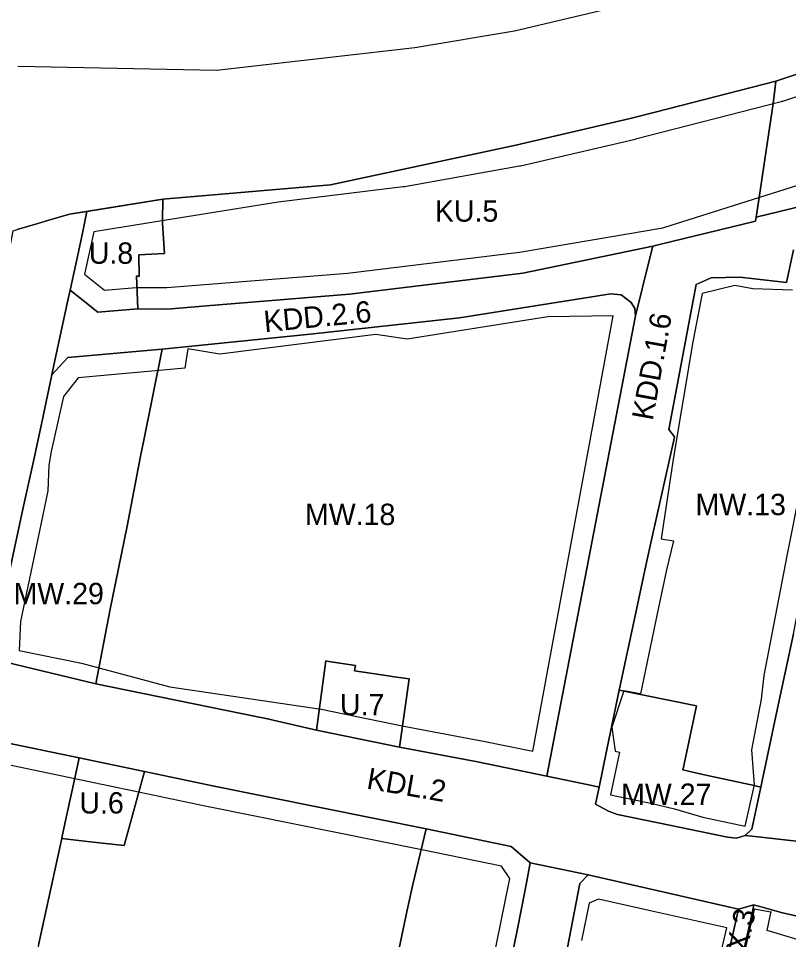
# Model space of a CAD drawing. Extents: x 7421913 to 7423341, y 5550123 to 5551175.
# Drawn here: x 7422221.1 to 7422401.5, y 5550727.7 to 5550943.3 of the extents above; entities that cross this region are included whole.
import ezdxf

# ---------------------------------------------------------------- set-up
doc = ezdxf.new("R2010")
doc.units = 0
for name, color, linetype in [('linie_rozgraniczajace', 7, 'Continuous'), ('linie_zabudowy_nieprzekraczalne', 7, 'Continuous'), ('oznaczenia_przeznaczen', 7, 'Continuous')]:
    doc.layers.add(name, color=color, linetype=linetype)

msp = doc.modelspace()

# ---------------------------------------------------------------- linework, layer by layer
at = {"layer": 'linie_rozgraniczajace'}
for points in [[(7422220.98, 5550932.17), (7422267.53, 5550931.27), (7422313.91, 5550936.52), (7422337.26, 5550940.47), (7422374.26, 5550949.25), (7422409.76, 5550960.93), (7422437.33, 5550971.35), (7422441.45, 5550972.91), (7422471.77, 5550984.38), (7422488.78, 5550990.81), (7422507.92, 5550998.54), (7422528.96, 5551007.2), (7422549.46, 5551014.98), (7422566.39, 5551020.72), (7422600.97, 5551030.45), (7422637.74, 5551037.63), (7422706.25, 5551050.46), (7422774.99, 5551065.83), (7422840.21, 5551081.98)], [(7422487.44, 5550952.92), (7422458.59, 5550942.31), (7422440.1, 5550939.32), (7422431.14, 5550942.19), (7422416.39, 5550936.46), (7422412.46, 5550934.94), (7422412.25, 5550934.1), (7422412.12, 5550933.61), (7422403.43, 5550930.26), (7422398.51, 5550928.69), (7422370.22, 5550921.41), (7422364.38, 5550919.91), (7422337.59, 5550913.65), (7422294.17, 5550904.39), (7422254.92, 5550901.03), (7422233.03, 5550897.49), (7422228.24, 5550896.09), (7422225.63, 5550895.33), (7422220.81, 5550893.92)], [(7422402.63, 5550889.21), (7422401, 5550881.52), (7422390.04, 5550882.81), (7422383.35, 5550882.62), (7422379.85, 5550881.03), (7422373.43, 5550847.12), (7422374.78, 5550845.38), (7422374.61, 5550844.64), (7422369.53, 5550821.98), (7422368.03, 5550815.31), (7422365.83, 5550804.99), (7422361.79, 5550786.12), (7422358.91, 5550772.22), (7422357.09, 5550763.43), (7422355.4, 5550763.78), (7422344.84, 5550765.96), (7422365.63, 5550873.73), (7422367.2, 5550880.07), (7422369.15, 5550887.93), (7422369.68, 5550890.05), (7422371.88, 5550890.58), (7422376.72, 5550891.74), (7422393.4, 5550895.8), (7422393.74, 5550895.88), (7422393.88, 5550896.84), (7422404.82, 5550899.45)], [(7422402.67, 5550799.3), (7422398.8, 5550781.52), (7422394.98, 5550763.42), (7422393.44, 5550763.78), (7422383.62, 5550765.92), (7422380.72, 5550766.55), (7422376.71, 5550767.42), (7422376.76, 5550767.69), (7422376.92, 5550768.48), (7422377.62, 5550771.73), (7422379.89, 5550782.4), (7422361.79, 5550786.12), (7422365.83, 5550804.99), (7422368.03, 5550815.31), (7422369.53, 5550821.98), (7422374.61, 5550844.64), (7422374.78, 5550845.38), (7422373.43, 5550847.12), (7422379.85, 5550881.03), (7422383.35, 5550882.62), (7422390.04, 5550882.81), (7422401, 5550881.52), (7422402.63, 5550889.21)], [(7422218.17, 5550792.64), (7422239.26, 5550787.57), (7422277.08, 5550779.86), (7422278.76, 5550779.52), (7422290.94, 5550776.76), (7422310.39, 5550772.77), (7422328.26, 5550769.39), (7422344.84, 5550765.96), (7422355.4, 5550763.78), (7422357.09, 5550763.43), (7422356.25, 5550759.4), (7422359.3, 5550757.74), (7422361.38, 5550757), (7422373.96, 5550754.42), (7422387.19, 5550751.67), (7422389.29, 5550751.47), (7422391.33, 5550752.11), (7422393.67, 5550751.85), (7422404, 5550750.7)], [(7422436.89, 5550725.5), (7422425.59, 5550727.79), (7422410.79, 5550730.73), (7422411.25, 5550731.36), (7422403.89, 5550733.09), (7422400.05, 5550733.99), (7422393.38, 5550735.82), (7422389.77, 5550734.83), (7422370.59, 5550739.24), (7422354.55, 5550742.84), (7422340.93, 5550745.68), (7422336.5, 5550749.5), (7422316.61, 5550753.63), (7422266.97, 5550763.62), (7422250.63, 5550767.05), (7422241.68, 5550768.92), (7422235.34, 5550770.25), (7422213.4, 5550774.82)], [(7422213.4, 5550774.82), (7422235.34, 5550770.25), (7422234.28, 5550765.52), (7422232.46, 5550757.03), (7422231.35, 5550751.91), (7422231.24, 5550751.35), (7422230.09, 5550746.05), (7422225.78, 5550726.41), (7422221.66, 5550706.89), (7422221.26, 5550704.88), (7422221.11, 5550704.1), (7422217.38, 5550687.41)], [(7422225.78, 5550726.41), (7422230.09, 5550746.05), (7422231.24, 5550751.35), (7422237.9, 5550750.63), (7422245.87, 5550749.77), (7422250.63, 5550767.05), (7422266.97, 5550763.62), (7422316.61, 5550753.63), (7422313.46, 5550740.58), (7422312.18, 5550734.61), (7422310.91, 5550728.65), (7422309.63, 5550722.69)], [(7422309.63, 5550722.69), (7422310.91, 5550728.65), (7422312.18, 5550734.61), (7422313.46, 5550740.58), (7422316.61, 5550753.63), (7422336.5, 5550749.5), (7422340.93, 5550745.68), (7422340.21, 5550741.37), (7422339.01, 5550735.36), (7422337.8, 5550729.42), (7422336.62, 5550723.39)], [(7422336.62, 5550723.39), (7422337.8, 5550729.42), (7422339.01, 5550735.36), (7422340.21, 5550741.37), (7422340.93, 5550745.68), (7422354.55, 5550742.84), (7422352.62, 5550740.82), (7422350.11, 5550727.89), (7422347.79, 5550715.72)], [(7422347.79, 5550715.72), (7422350.11, 5550727.89), (7422352.62, 5550740.82), (7422354.55, 5550742.84), (7422370.59, 5550739.24), (7422389.77, 5550734.83), (7422386.06, 5550718.57)]]:
    msp.add_lwpolyline(points, dxfattribs=at)
for points in [[(7422404.82, 5550899.45), (7422393.88, 5550896.84), (7422394.59, 5550901.4), (7422397.89, 5550923.41), (7422398.27, 5550926.65), (7422398.51, 5550928.69), (7422403.43, 5550930.26), (7422412.12, 5550933.61), (7422412.25, 5550934.1), (7422412.46, 5550934.94), (7422416.39, 5550936.46), (7422431.14, 5550942.19), (7422429, 5550931.44), (7422425.22, 5550912.43), (7422423.53, 5550903.95)], [(7422254.92, 5550901.03), (7422294.17, 5550904.39), (7422337.59, 5550913.65), (7422364.38, 5550919.91), (7422370.22, 5550921.41), (7422398.51, 5550928.69), (7422398.27, 5550926.65), (7422397.89, 5550923.41), (7422394.59, 5550901.4), (7422393.88, 5550896.84), (7422393.74, 5550895.88), (7422393.4, 5550895.8), (7422376.72, 5550891.74), (7422371.88, 5550890.58), (7422369.68, 5550890.05), (7422339.28, 5550883.68), (7422298.68, 5550878.76), (7422265.17, 5550876.07), (7422256.05, 5550875.32), (7422249.09, 5550875.36), (7422248.73, 5550883.07), (7422249.37, 5550882.92), (7422249.29, 5550888.04), (7422252.28, 5550888.19), (7422255.28, 5550888.34), (7422254.87, 5550895.34), (7422254.83, 5550895.99), (7422254.88, 5550895.99)], [(7422233.22, 5550879.76), (7422234.52, 5550885.8), (7422236.08, 5550893.09), (7422237.14, 5550898.15), (7422254.92, 5550901.03), (7422254.88, 5550895.99), (7422254.83, 5550895.99), (7422254.87, 5550895.34), (7422255.28, 5550888.34), (7422252.28, 5550888.19), (7422249.29, 5550888.04), (7422249.37, 5550882.92), (7422248.73, 5550883.07), (7422249.09, 5550875.36), (7422239.72, 5550874.56)], [(7422218.13, 5550809.87), (7422216.61, 5550802.89), (7422215.46, 5550803.43), (7422210.18, 5550805.96), (7422209.07, 5550806.49), (7422206.35, 5550807.8), (7422203.81, 5550809.68), (7422219.88, 5550893.65), (7422220.81, 5550893.92), (7422225.63, 5550895.33), (7422228.24, 5550896.09), (7422233.03, 5550897.49), (7422237.14, 5550898.15), (7422236.08, 5550893.09), (7422234.52, 5550885.8), (7422233.22, 5550879.76), (7422232.78, 5550877.73), (7422229.43, 5550862.16), (7422228.94, 5550859.89), (7422226.56, 5550848.79), (7422225.93, 5550845.85), (7422224.91, 5550841.13), (7422222.32, 5550829.17)], [(7422367.2, 5550880.07), (7422365.63, 5550873.73), (7422365.45, 5550875.47), (7422364.61, 5550876.81), (7422362.31, 5550878.65), (7422359.85, 5550878.91), (7422324.42, 5550873.29), (7422289.47, 5550869.45), (7422254.74, 5550865.96), (7422232.68, 5550864), (7422228.94, 5550859.89), (7422229.43, 5550862.16), (7422232.78, 5550877.73), (7422233.22, 5550879.76), (7422239.72, 5550874.56), (7422249.09, 5550875.36), (7422256.05, 5550875.32), (7422265.17, 5550876.07), (7422298.68, 5550878.76), (7422339.28, 5550883.68), (7422369.68, 5550890.05), (7422369.15, 5550887.93)], [(7422429.98, 5550882.78), (7422423.8, 5550851.32), (7422423.18, 5550848.17), (7422422.74, 5550845.9), (7422421.6, 5550840.11), (7422420.88, 5550836.46), (7422412.36, 5550793.58), (7422404.93, 5550755.58), (7422404, 5550750.7), (7422393.67, 5550751.85), (7422391.33, 5550752.11), (7422392.9, 5550753.58), (7422394.98, 5550763.42), (7422398.8, 5550781.52), (7422402.67, 5550799.3), (7422406.26, 5550817.72), (7422411.97, 5550845.88), (7422415.62, 5550865.28), (7422419.77, 5550885.08), (7422429.13, 5550882.96)], [(7422246.55, 5550824.45), (7422249.81, 5550841.29), (7422250.39, 5550844.23), (7422254.74, 5550865.96), (7422289.47, 5550869.45), (7422324.42, 5550873.29), (7422359.85, 5550878.91), (7422362.31, 5550878.65), (7422364.61, 5550876.81), (7422365.45, 5550875.47), (7422365.63, 5550873.73), (7422344.84, 5550765.96), (7422328.26, 5550769.39), (7422310.39, 5550772.77), (7422312.63, 5550788.72), (7422309.12, 5550789.25), (7422307.68, 5550789.46), (7422299.84, 5550790.63), (7422300.05, 5550791.88), (7422293.8, 5550792.83), (7422293.13, 5550792.93), (7422290.94, 5550776.76), (7422278.76, 5550779.52), (7422277.08, 5550779.86), (7422239.26, 5550787.57), (7422242.62, 5550805.06)], [(7422242.62, 5550805.06), (7422239.26, 5550787.57), (7422218.17, 5550792.64), (7422216.18, 5550795.44), (7422216.61, 5550802.89), (7422218.13, 5550809.87), (7422222.32, 5550829.17), (7422224.91, 5550841.13), (7422225.93, 5550845.85), (7422226.56, 5550848.79), (7422228.94, 5550859.89), (7422232.68, 5550864), (7422254.74, 5550865.96), (7422250.39, 5550844.23), (7422249.81, 5550841.29), (7422246.55, 5550824.45)], [(7422310.39, 5550772.77), (7422290.94, 5550776.76), (7422293.13, 5550792.93), (7422293.8, 5550792.83), (7422300.05, 5550791.88), (7422299.84, 5550790.63), (7422307.68, 5550789.46), (7422309.12, 5550789.25), (7422312.63, 5550788.72)], [(7422394.98, 5550763.42), (7422392.9, 5550753.58), (7422391.33, 5550752.11), (7422389.29, 5550751.47), (7422387.19, 5550751.67), (7422373.96, 5550754.42), (7422361.38, 5550757), (7422359.3, 5550757.74), (7422356.25, 5550759.4), (7422357.09, 5550763.43), (7422358.91, 5550772.22), (7422361.79, 5550786.12), (7422379.89, 5550782.4), (7422377.62, 5550771.73), (7422376.92, 5550768.48), (7422376.76, 5550767.69), (7422376.71, 5550767.42), (7422380.72, 5550766.55), (7422383.62, 5550765.92), (7422393.44, 5550763.78)], [(7422250.63, 5550767.05), (7422245.87, 5550749.77), (7422237.9, 5550750.63), (7422231.24, 5550751.35), (7422231.35, 5550751.91), (7422232.46, 5550757.03), (7422234.28, 5550765.52), (7422235.34, 5550770.25), (7422241.68, 5550768.92)], [(7422388.85, 5550715.6), (7422386.06, 5550718.57), (7422389.77, 5550734.83), (7422393.38, 5550735.82), (7422392.79, 5550733.16), (7422391.17, 5550725.97)], [(7422454.96, 5550722.08), (7422451.28, 5550712.14), (7422483.54, 5550700.93), (7422481.91, 5550688.66), (7422474.43, 5550684.56), (7422444.95, 5550694.93), (7422433.33, 5550699.08), (7422427.58, 5550701.09), (7422417.05, 5550704.79), (7422403.17, 5550709.84), (7422389.47, 5550714.93), (7422388.85, 5550715.6), (7422391.17, 5550725.97), (7422392.79, 5550733.16), (7422393.38, 5550735.82), (7422400.05, 5550733.99), (7422403.89, 5550733.09), (7422411.25, 5550731.36), (7422410.79, 5550730.73), (7422425.59, 5550727.79), (7422436.89, 5550725.5), (7422442.35, 5550724.39)]]:
    msp.add_lwpolyline(points, close=True, dxfattribs=at)
at = {"layer": 'linie_zabudowy_nieprzekraczalne'}
for points in [[(7422404.95, 5550925.5), (7422400.03, 5550923.93), (7422399.8, 5550923.86), (7422399.76, 5550923.85), (7422365.63, 5550915.07), (7422365.52, 5550915.04), (7422338.73, 5550908.78), (7422338.57, 5550908.75), (7422338.47, 5550908.73), (7422311.51, 5550903.93), (7422311.28, 5550903.89), (7422311.23, 5550903.89), (7422281.93, 5550900.33), (7422255.72, 5550896.09), (7422238.79, 5550893.37), (7422236.6, 5550883.46), (7422241.28, 5550879.71), (7422248.66, 5550880.34), (7422248.76, 5550880.35), (7422249.09, 5550880.36), (7422249.12, 5550880.36), (7422255.86, 5550880.32), (7422264.76, 5550881.05), (7422264.77, 5550881.05), (7422298.17, 5550883.74), (7422338.47, 5550888.62), (7422372.01, 5550894.36), (7422403.66, 5550904.31)], [(7422402.4, 5550879.72), (7422393.12, 5550880.04), (7422388.92, 5550880.82), (7422381.22, 5550878.99), (7422379.06, 5550867.66), (7422374.5, 5550840.65), (7422371.62, 5550821.56), (7422374.5, 5550821.04), (7422372.91, 5550814.24), (7422370.72, 5550803.95), (7422370.72, 5550803.94), (7422366.79, 5550785.22), (7422362.91, 5550785.96), (7422360.08, 5550777.41), (7422360.87, 5550771.85), (7422361.92, 5550771.59), (7422359.77, 5550761.62), (7422369.52, 5550759.53), (7422374.76, 5550758.32), (7422381.42, 5550756.33), (7422391.32, 5550754.25), (7422393.49, 5550763.93), (7422392.91, 5550772.11), (7422395.16, 5550784.02), (7422395.79, 5550789.57), (7422401.14, 5550817.58), (7422404.34, 5550833.63)], [(7422345.09, 5550873.47), (7422312.15, 5550868.25), (7422304.81, 5550869.37), (7422268.28, 5550864.75), (7422260.81, 5550866.01), (7422260.08, 5550861.49), (7422235.07, 5550859.19), (7422231.64, 5550854.87), (7422230.34, 5550848.9), (7422228.75, 5550842), (7422228.19, 5550838.74), (7422228.01, 5550832.77), (7422226.05, 5550823.36), (7422221.58, 5550802.21), (7422221.3, 5550795.39), (7422235.84, 5550792.41), (7422256.54, 5550786.91), (7422291.99, 5550781.65), (7422311.36, 5550777.68), (7422329.19, 5550774.3), (7422329.24, 5550774.29), (7422329.27, 5550774.29), (7422341.61, 5550771.79), (7422360.38, 5550873.72), (7422345.09, 5550873.47)], [(7422324.7, 5550685.55), (7422336.17, 5550742.05), (7422334.22, 5550744.87), (7422315.61, 5550748.73), (7422265.98, 5550758.72), (7422265.94, 5550758.73), (7422249.61, 5550762.16), (7422240.66, 5550764.03), (7422240.65, 5550764.03), (7422234.32, 5550765.36), (7422214.9, 5550769.4)], [(7422357, 5550737.16), (7422354.76, 5550736.26), (7422352.98, 5550727.49)], [(7422382.17, 5550709.87), (7422387.01, 5550730.48), (7422369.48, 5550734.36), (7422357, 5550737.16)], [(7422397.31, 5550734.1), (7422393.4, 5550734.85), (7422389.39, 5550716.95), (7422402.44, 5550712.28), (7422408.31, 5550709.95), (7422417.64, 5550706.69), (7422427.89, 5550702.59), (7422456.51, 5550692.24), (7422459.96, 5550690), (7422467.33, 5550687.39), (7422480.75, 5550693.45), (7422482.8, 5550707.62), (7422483.27, 5550712.28), (7422460.61, 5550720.12), (7422459.4, 5550716.2), (7422441.37, 5550719.49), (7422441.35, 5550719.49), (7422435.9, 5550720.6), (7422424.61, 5550722.89), (7422409.18, 5550726), (7422396.47, 5550729.81), (7422397.4, 5550734.29)]]:
    msp.add_lwpolyline(points, dxfattribs=at)

# ---------------------------------------------------------------- texts
at = {"layer": 'oznaczenia_przeznaczen'}
for s, p in [('KU.5', (7422318.64, 5550895.76)), ('U.8', (7422237.58, 5550885.91)), ('MW.13', (7422379.68, 5550827.06)), ('MW.18', (7422288.21, 5550824.75)), ('MW.29', (7422219.95, 5550806.22)), ('U.7', (7422296.41, 5550780.22)), ('MW.27', (7422362.25, 5550759.24)), ('U.6', (7422235.38, 5550757.22))]:
    msp.add_text(s, height=5, dxfattribs=at).set_placement(p)
for s, rotation, p in [('KDD.2.6', 5.5026, (7422278.8, 5550869.88)), ('KDD.1.6', 79.6795, (7422369.65, 5550849.04)), ('KDL.2', 350.1066, (7422302.45, 5550763.09)), ('KDX.3', 77.5331, (7422389.65, 5550715.42))]:
    msp.add_text(s, height=5, rotation=rotation, dxfattribs=at).set_placement(p)

doc.saveas('drawing.dxf')
